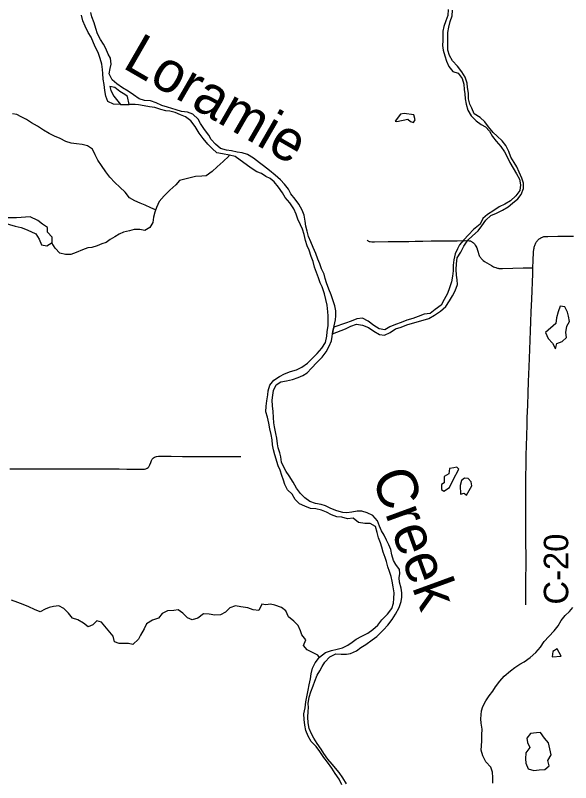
# Model space of a CAD drawing. Extents: x -87 to 2145, y -2128 to 440.
# Drawn here: x 154.2 to 188.26, y -1010.07 to -963.04 of the extents above; entities that cross this region are included whole.
import ezdxf

# ---------------------------------------------------------------- set-up
doc = ezdxf.new("R2010")
doc.units = 0
for name, color, linetype in [('GM_X_County_Road', 7, 'Continuous'), ('GM_X_County_Road_Text', 7, 'Continuous'), ('GM_X_Major_River', 7, 'Continuous'), ('GM_X_Major_River_Text', 7, 'Continuous'), ('GM_X_Minor_Lake', 7, 'Continuous'), ('GM_X_Minor_River', 7, 'Continuous'), ('GM_X_Township_Road', 7, 'Continuous')]:
    doc.layers.add(name, color=color, linetype=linetype)

msp = doc.modelspace()

# ---------------------------------------------------------------- linework, layer by layer
at = {"layer": 'GM_X_County_Road'}
for points in [[(185.948, -978.508), (185.962, -978.073), (185.991, -977.55), (186.009, -977.375), (186.019, -977.311), (186.031, -977.245), (186.046, -977.194), (186.064, -977.138), (186.083, -977.085), (186.105, -977.036), (186.128, -976.989), (186.151, -976.95), (186.171, -976.919), (186.203, -976.876), (186.236, -976.835), (186.267, -976.8), (186.298, -976.77), (186.339, -976.735), (186.38, -976.706), (186.428, -976.677), (186.479, -976.649), (186.536, -976.626), (186.581, -976.61), (186.623, -976.6), (186.679, -976.592), (186.729, -976.589), (186.853, -976.586), (187.475, -976.572), (188.147, -976.569), (188.443, -976.566)], [(185.534, -990.215), (185.537, -989.924), (185.548, -989.514), (185.573, -988.727), (185.588, -988.203), (185.604, -987.711), (185.634, -986.924), (185.658, -986.187), (185.685, -985.482), (185.724, -984.581), (185.767, -983.515), (185.806, -982.368), (185.827, -981.827), (185.85, -981.221), (185.881, -980.434), (185.936, -978.877), (185.948, -978.508)], [(185.517, -999.171), (185.52, -997.581), (185.525, -996.728), (185.525, -996.154), (185.518, -995.4), (185.518, -994.596), (185.516, -993.941), (185.521, -992.99), (185.518, -992.318), (185.517, -991.99), (185.523, -991.301), (185.53, -990.613), (185.534, -990.215)]]:
    msp.add_lwpolyline(points, dxfattribs=at)
at = {"layer": 'GM_X_Major_River'}
for p, q in [((161.172, -968.496), (161.07, -968.011)), ((160.646, -968.494), (161.172, -968.496)), ((161.551, -968.503), (161.172, -968.496))]:
    msp.add_line(p, q, dxfattribs=at)
for points in [[(158.338, -963.372), (158.265, -963.018)], [(170.175, -988.673), (170.092, -988.268), (170.057, -988.016), (170.033, -987.683), (170.009, -987.33), (169.975, -986.976), (169.962, -986.634), (169.988, -986.312), (170.043, -986.041), (170.201, -985.681), (170.475, -985.495), (170.828, -985.431), (171.191, -985.367), (171.555, -985.243), (171.839, -985.107), (172.093, -984.941), (172.359, -984.663), (172.687, -984.317), (173.015, -983.981), (173.272, -983.663), (173.459, -983.314), (173.586, -982.994), (173.641, -982.723), (173.677, -982.401), (173.754, -982.07), (173.841, -981.709), (173.856, -981.447), (173.851, -981.145), (173.797, -980.852), (173.702, -980.527), (173.578, -980.172), (173.434, -979.817), (173.28, -979.441), (173.205, -979.158), (173.14, -978.905), (172.975, -978.569), (172.87, -978.275), (172.755, -977.991), (172.631, -977.636), (172.467, -977.27), (172.322, -976.925), (172.188, -976.59), (172.104, -976.266), (172.019, -975.952), (171.984, -975.649), (171.921, -975.295), (171.796, -974.97), (171.592, -974.614), (171.367, -974.297), (171.101, -973.97), (170.946, -973.695), (170.7, -973.388), (170.474, -973.122), (170.138, -972.833), (169.782, -972.545), (169.425, -972.266), (169.168, -972.069), (168.801, -971.801), (168.434, -971.562), (168.114, -971.465), (167.813, -971.429), (167.463, -971.352), (167.143, -971.296), (166.783, -971.199), (166.486, -970.931), (166.21, -970.654), (166.064, -970.389), (165.81, -970.032), (165.565, -969.674), (165.42, -969.41), (165.094, -969.091), (164.755, -968.964), (164.394, -968.927), (164.064, -968.83), (163.804, -968.755), (163.525, -968.659), (163.175, -968.561), (162.836, -968.394), (162.487, -968.287), (162.126, -968.26), (161.786, -968.152), (161.449, -967.914), (161.122, -967.687), (160.774, -967.479), (160.427, -967.23), (160.13, -966.993), (159.956, -966.627), (160.012, -966.285), (160.067, -966.024), (160.034, -965.671), (159.898, -965.417), (159.754, -965.071), (159.608, -964.807), (159.432, -964.511), (159.248, -964.165), (159.133, -963.851), (159.029, -963.496), (158.895, -963.131), (158.82, -962.857)], [(160.646, -968.494), (160.223, -968.476), (159.864, -968.318), (159.75, -967.983), (159.686, -967.639), (159.652, -967.276), (159.588, -966.952), (159.564, -966.599), (159.539, -966.347), (159.495, -966.034), (159.4, -965.689), (159.277, -965.324), (159.112, -964.999), (158.997, -964.715), (158.852, -964.369), (158.667, -964.084), (158.473, -963.697), (158.338, -963.372)], [(161.07, -968.011), (160.907, -967.894), (160.609, -967.697), (160.292, -967.459), (159.992, -967.393), (160.057, -967.646), (160.242, -967.992), (160.646, -968.494)], [(169.661, -987.676), (169.567, -987.341), (169.583, -986.989), (169.63, -986.658), (169.677, -986.296), (169.701, -986.044), (169.818, -985.714), (170.055, -985.396), (170.401, -985.181), (170.715, -985.015), (171.08, -984.861), (171.443, -984.757), (171.768, -984.612), (172.114, -984.357), (172.717, -983.773), (173.005, -983.436), (173.232, -983.098), (173.3, -982.696), (173.325, -982.435), (173.383, -982.043), (173.398, -981.761), (173.383, -981.458), (173.358, -981.206), (173.335, -980.793), (173.241, -980.458), (173.167, -980.104), (173.014, -979.688), (172.899, -979.434), (172.804, -979.13), (172.669, -978.795), (172.545, -978.47), (172.471, -978.126), (172.346, -977.812), (172.232, -977.437), (172.107, -977.163), (172.002, -976.838), (171.919, -976.464), (171.804, -976.149), (171.689, -975.875), (171.535, -975.53), (171.43, -975.215), (171.275, -974.89), (171.031, -974.523), (170.745, -974.205), (170.58, -973.91), (170.345, -973.573), (170.08, -973.235), (169.823, -973.029), (169.564, -972.913), (169.296, -972.737), (169.017, -972.621), (168.659, -972.413), (168.352, -972.175), (167.995, -971.916), (167.688, -971.699), (167.328, -971.612), (166.907, -971.533), (166.567, -971.456), (166.27, -971.209), (166.014, -970.942), (165.719, -970.584), (165.474, -970.267), (165.23, -969.849), (164.955, -969.512), (164.629, -969.264), (164.32, -969.127), (164.001, -969), (163.671, -968.913), (163.42, -968.899), (163.12, -968.812), (162.761, -968.685), (162.43, -968.638), (162.109, -968.592), (161.759, -968.525), (161.551, -968.503)], [(174.235, -1010.198), (174.071, -1009.853), (173.826, -1009.506), (173.611, -1009.179), (173.356, -1008.822), (173.121, -1008.525), (172.886, -1008.168), (172.661, -1007.862), (172.355, -1007.554), (172.151, -1007.218), (172.016, -1006.873), (171.962, -1006.549), (171.918, -1006.206), (171.905, -1005.853), (171.972, -1005.492), (172.019, -1005.12), (172.153, -1004.397), (172.219, -1004.066), (172.306, -1003.715), (172.352, -1003.393), (172.419, -1003.052), (172.596, -1002.723), (172.863, -1002.385), (173.22, -1002.1), (173.584, -1001.976), (173.938, -1001.881), (174.271, -1001.807), (174.595, -1001.642), (174.85, -1001.465), (175.105, -1001.269), (175.459, -1001.094), (175.814, -1000.909), (176.12, -1000.683), (176.426, -1000.427), (176.674, -1000.089), (177.022, -999.743), (177.289, -999.405), (177.386, -999.075), (177.411, -998.793), (177.428, -998.441), (177.384, -998.067), (177.321, -997.713), (177.245, -997.44), (177.14, -997.136), (177.056, -996.842), (176.961, -996.518), (176.875, -996.264), (176.771, -995.94), (176.676, -995.646), (176.591, -995.372), (176.466, -995.058), (176.391, -994.734), (176.288, -994.379), (175.97, -994.192), (175.628, -994.186), (175.247, -994.128), (174.931, -993.86), (174.568, -993.904), (174.229, -993.807), (173.918, -993.771), (173.599, -993.654), (173.28, -993.497), (172.971, -993.37), (172.641, -993.293), (172.3, -993.257), (171.961, -993.119), (171.632, -992.982), (171.356, -992.705), (171.171, -992.389), (170.894, -992.122), (170.72, -991.796), (170.654, -991.533), (170.549, -991.249), (170.445, -990.915), (170.329, -990.65), (170.121, -989.982), (170.036, -989.678), (169.981, -989.364), (169.947, -989.051), (169.883, -988.728), (169.809, -988.374), (169.755, -988.03), (169.661, -987.676)], [(174.507, -1010.143), (174.293, -1009.776), (174.068, -1009.45), (173.636, -1008.938), (173.36, -1008.631), (173.125, -1008.294), (172.959, -1008.029), (172.705, -1007.681), (172.51, -1007.335), (172.364, -1007.081), (172.23, -1006.746), (172.166, -1006.412), (172.132, -1006.049), (172.158, -1005.717), (172.173, -1005.465), (172.168, -1005.213), (172.225, -1004.841), (172.322, -1004.501), (172.469, -1004.131), (172.565, -1003.86), (172.712, -1003.49), (172.868, -1003.211), (173.014, -1002.952), (173.179, -1002.693), (173.497, -1002.367), (173.852, -1002.182), (174.193, -1002.199), (174.514, -1002.205), (174.767, -1002.149), (175.131, -1001.984), (175.396, -1001.788), (175.691, -1001.602), (176.078, -1001.327), (176.373, -1001.111), (176.783, -1000.696), (177.039, -1000.408), (177.307, -1000.061), (177.524, -999.742), (177.742, -999.343), (177.87, -998.973), (177.905, -998.702), (177.9, -998.43), (177.865, -998.157), (177.771, -997.782), (177.746, -997.51), (177.781, -997.259), (177.756, -997.006), (177.53, -996.7), (177.404, -996.446), (177.3, -996.111), (177.236, -995.777), (177.111, -995.493), (176.975, -995.208), (176.831, -994.893), (176.655, -994.628), (176.529, -994.344), (176.415, -994.019), (176.13, -993.691), (175.781, -993.523), (175.461, -993.427), (175.16, -993.421), (174.847, -993.486), (174.535, -993.54), (174.284, -993.516), (173.924, -993.418), (173.556, -993.27), (173.217, -993.103), (172.957, -993.027), (172.607, -992.95), (172.258, -992.833), (171.95, -992.615), (171.684, -992.338), (171.439, -992.011), (171.245, -991.645), (171.001, -991.257), (170.805, -991.002), (170.65, -990.687), (170.524, -990.432), (170.48, -990.109), (170.414, -989.856), (170.329, -989.552), (170.284, -989.299), (170.23, -988.946), (170.175, -988.673)]]:
    msp.add_lwpolyline(points, dxfattribs=at)
at = {"layer": 'GM_X_Minor_Lake'}
for points in [[(178.043, -969.045), (177.831, -969.101), (177.501, -969.528), (177.601, -969.55), (178.267, -969.403)], [(178.267, -969.403), (178.434, -969.547), (178.624, -969.602), (178.718, -969.442), (178.634, -969.128), (178.043, -969.045)], [(155.114, -975.379), (154.278, -975.448), (153.967, -975.441), (153.645, -975.455), (153.394, -975.48), (153.499, -975.754), (153.848, -975.862), (154.198, -975.95), (154.557, -976.048), (154.816, -976.144), (155.155, -976.282), (155.463, -976.43)], [(155.463, -976.43), (155.657, -976.766), (155.8, -977.112), (156.121, -977.159), (156.466, -976.965), (156.453, -976.642), (156.178, -976.334), (156.174, -976.032), (155.867, -975.844), (155.571, -975.606), (155.114, -975.379)], [(188.031, -982.099), (188.182, -981.802), (188.133, -981.479), (188.072, -981.225), (187.912, -980.897), (187.623, -980.856), (187.49, -981.204), (187.387, -981.582), (187.345, -981.923)], [(187.345, -981.923), (186.713, -982.484), (186.88, -982.853), (187.141, -983.134), (187.33, -983.483), (187.422, -983.144), (187.747, -983.035), (188.016, -982.793), (187.968, -982.469), (188.031, -982.099)], [(181.057, -991.502), (181.4, -990.86), (181.275, -990.724), (181.092, -990.778), (180.83, -990.809), (180.799, -991.14), (180.512, -991.311)], [(180.512, -991.311), (180.498, -991.683), (180.344, -991.798), (180.343, -992.1), (180.49, -992.196), (180.829, -991.987), (181.057, -991.502)], [(182.198, -991.875), (182.166, -991.642), (181.982, -991.434), (181.742, -991.416), (181.567, -991.55), (181.486, -991.86)], [(181.486, -991.86), (181.497, -992.393), (181.72, -992.331), (181.876, -992.457), (182.198, -991.875)], [(187.168, -1002.03), (187.127, -1002.361), (187.674, -1002.318)], [(187.674, -1002.318), (187.445, -1001.859), (187.168, -1002.03)], [(186.333, -1009.279), (186.673, -1009.259), (186.952, -1009.038), (186.853, -1008.712), (187.066, -1008.358), (186.978, -1007.992), (186.911, -1007.637), (186.65, -1007.346), (186.421, -1007.006), (186.17, -1007.017), (185.807, -1007.064)], [(185.807, -1007.064), (185.566, -1007.347), (185.617, -1007.601), (185.757, -1007.918), (185.514, -1008.251), (185.502, -1008.603), (185.522, -1008.876), (185.661, -1009.223), (186.008, -1009.336), (186.333, -1009.279)]]:
    msp.add_lwpolyline(points, dxfattribs=at)
at = {"layer": 'GM_X_Minor_River'}
msp.add_line((178.205, -982.012), (179.569, -981.613), dxfattribs=at)
for points in [[(180.757, -962.68), (180.724, -963.041), (180.602, -963.379), (180.489, -963.727), (180.429, -963.997), (180.428, -964.319), (180.419, -964.57), (180.408, -964.892), (180.438, -965.165), (180.546, -965.521), (180.646, -965.837), (180.784, -966.174), (181.044, -966.485), (181.372, -966.588), (181.612, -966.898), (181.7, -967.254), (181.738, -967.587), (181.779, -967.84), (181.798, -968.153), (181.847, -968.487), (181.955, -968.843), (182.153, -969.203), (182.464, -969.496), (182.767, -969.718), (183.032, -969.879), (183.284, -970.14), (183.473, -970.469), (183.694, -970.758), (183.974, -971.07), (184.213, -971.401), (184.391, -971.75), (184.541, -972.067), (184.73, -972.396), (184.948, -972.746), (185.127, -973.085), (185.185, -973.419), (185.153, -973.771), (184.9, -974.104), (184.579, -974.404), (184.23, -974.613), (183.883, -974.782), (183.544, -975.001), (183.165, -975.239), (182.885, -975.481), (182.702, -975.827), (182.309, -976.155), (181.996, -976.496), (181.715, -976.798), (181.443, -977.1), (181.314, -977.357), (181.173, -977.664), (181.09, -978.024), (181.058, -978.355), (181.046, -978.706), (181.024, -979.028), (180.952, -979.368), (180.838, -979.746), (180.716, -980.094), (180.513, -980.449), (180.31, -980.794), (179.959, -981.063), (179.639, -981.313)], [(180.277, -981.165), (180.598, -980.885), (180.831, -980.531), (181.012, -980.225), (181.173, -979.929), (181.327, -979.542), (181.297, -979.259), (181.268, -978.956), (181.24, -978.613), (181.252, -978.261), (181.305, -977.9), (181.518, -977.556), (181.711, -977.19), (181.945, -976.826), (182.245, -976.555), (182.587, -976.255), (182.819, -975.931), (183.062, -975.598), (183.373, -975.307), (183.719, -975.159), (184.077, -974.98), (184.425, -974.781), (184.704, -974.55), (185.015, -974.279), (185.224, -974.025), (185.378, -973.658), (185.37, -973.315), (185.26, -973.009), (185.112, -972.642), (184.953, -972.324), (184.792, -972.056), (184.593, -971.727), (184.464, -971.38), (184.296, -971.022), (184.056, -970.731), (183.755, -970.438), (183.502, -970.208), (183.213, -969.875), (182.993, -969.555), (182.712, -969.293), (182.348, -969.069), (182.199, -968.731), (182.078, -968.475), (181.999, -968.15), (181.991, -967.808), (181.943, -967.454), (181.912, -967.201), (181.795, -966.824), (181.596, -966.495), (181.317, -966.153), (181.007, -965.819), (180.828, -965.501), (180.729, -965.165), (180.721, -964.823), (180.734, -964.461), (180.737, -964.088), (180.789, -963.758), (180.871, -963.419), (180.984, -963.06), (181.016, -962.729)], [(162.801, -974.967), (162.516, -974.835), (162.168, -974.677), (161.859, -974.549), (161.531, -974.411), (161.203, -974.233), (160.939, -973.885), (160.615, -973.566), (160.299, -973.277), (159.985, -972.948), (159.741, -972.621), (159.487, -972.243), (159.253, -971.916), (159.089, -971.59), (158.926, -971.244), (158.629, -971.026), (158.299, -970.959), (157.959, -970.911), (157.618, -970.874), (157.288, -970.776), (156.951, -970.588), (156.593, -970.439), (156.265, -970.271), (155.917, -970.072), (155.551, -969.833), (155.183, -969.624), (154.876, -969.426), (154.559, -969.248), (154.29, -969.122), (154.03, -969.066)], [(167.313, -971.609), (167.303, -971.661), (166.944, -972.006), (166.586, -972.331), (166.268, -972.617), (165.901, -972.881), (165.63, -972.885), (165.258, -972.908), (164.915, -972.991), (164.602, -973.086), (164.278, -973.169), (164.042, -973.426), (163.684, -973.751), (163.325, -974.106), (163.026, -974.453), (162.858, -974.822), (162.752, -975.092), (162.675, -975.413), (162.628, -975.734), (162.451, -976.032), (162.146, -976.228), (161.826, -976.16), (161.494, -976.174), (161.211, -976.248), (160.838, -976.331), (160.564, -976.456), (160.31, -976.612), (160.015, -976.787), (159.76, -976.953), (159.508, -977.039), (159.214, -977.163), (158.9, -977.258), (158.649, -977.293), (158.315, -977.406), (157.93, -977.57), (157.606, -977.704), (157.285, -977.687), (156.924, -977.619), (156.65, -977.311), (156.427, -976.987)], [(179.639, -981.313), (179.273, -981.347), (178.918, -981.502), (178.584, -981.627), (178.221, -981.731), (177.857, -981.855), (177.513, -981.989), (177.178, -982.134), (176.854, -982.31), (176.523, -982.243), (176.185, -982.045), (175.849, -981.777), (175.5, -981.609), (175.138, -981.643), (174.794, -981.787), (174.46, -981.902), (173.737, -982.143)], [(179.569, -981.613), (179.907, -981.414), (180.277, -981.165)], [(173.658, -982.569), (174.454, -982.244), (174.788, -982.089), (175.132, -981.965), (175.492, -982.032), (175.852, -982.17), (176.189, -982.388), (176.537, -982.606), (176.837, -982.642), (177.192, -982.487), (177.518, -982.251), (177.861, -982.147), (178.205, -982.012)], [(173.737, -982.143), (173.677, -982.401), (173.658, -982.569)], [(160.199, -1001.09), (159.474, -1000.238), (159.205, -1000.152), (158.949, -1000.388), (158.664, -1000.523), (158.388, -1000.286), (158.031, -1000.087), (157.702, -999.979), (157.467, -999.692), (157.181, -999.404), (156.874, -999.237), (156.541, -999.28), (156.279, -999.345), (156.026, -999.43), (155.731, -999.606), (155.382, -999.467), (155.025, -999.299), (154.686, -999.16), (154.347, -999.033), (153.969, -998.884)], [(172.851, -1002.401), (172.758, -1002.26), (172.391, -1002.071), (172.102, -1001.934), (171.877, -1001.657), (172.015, -1001.307), (171.78, -1001.01), (171.695, -1000.757), (171.541, -1000.431), (171.276, -1000.174), (170.96, -999.905), (170.797, -999.549), (170.53, -999.342), (170.111, -999.202), (169.841, -999.136), (169.569, -999.171), (169.309, -999.125), (169.14, -999.514), (168.779, -999.487), (168.451, -999.359), (168.03, -999.3), (167.71, -999.243), (167.366, -999.356), (167.099, -999.623), (166.775, -999.777), (166.443, -999.8), (166.092, -999.753), (165.732, -999.715), (165.394, -999.99), (165.051, -1000.083), (164.752, -999.966), (164.467, -999.678), (164.18, -999.481), (163.928, -999.516), (163.526, -999.538), (163.201, -999.712), (162.974, -999.999), (162.62, -1000.113), (162.254, -1000.337), (162.097, -1000.646), (161.878, -1001.024), (161.762, -1001.284), (161.404, -1001.598), (161.134, -1001.542), (160.813, -1001.536), (160.561, -1001.54), (160.282, -1001.444), (160.199, -1001.09)], [(183.482, -1010.101), (183.494, -1009.759), (183.476, -1009.426), (183.366, -1009.12), (183.067, -1008.787), (182.869, -1008.418), (182.781, -1008.073), (182.79, -1007.821), (182.821, -1007.5), (182.824, -1007.138), (182.826, -1006.786), (182.769, -1006.421), (182.758, -1006.169), (182.767, -1005.918), (182.796, -1005.667), (182.885, -1005.409), (183.058, -1005.063), (183.269, -1004.748), (183.48, -1004.464), (183.66, -1004.199), (183.913, -1003.855), (184.185, -1003.553), (184.578, -1003.215), (184.835, -1003.023), (185.154, -1002.813), (185.42, -1002.662), (185.781, -1002.393), (186.122, -1002.103), (186.405, -1001.761), (186.628, -1001.417), (186.92, -1001.105), (187.243, -1000.774), (187.505, -1000.462), (187.677, -1000.136), (187.928, -999.833), (188.188, -999.58), (188.388, -999.326)]]:
    msp.add_lwpolyline(points, dxfattribs=at)
at = {"layer": 'GM_X_Township_Road'}
for points in [[(175.78, -976.827), (175.806, -976.847), (175.833, -976.864), (175.863, -976.879), (175.9, -976.892), (175.934, -976.902), (175.974, -976.907), (176.072, -976.915), (176.236, -976.919), (177.072, -976.906), (177.614, -976.903), (178.335, -976.894), (178.729, -976.883), (179.19, -976.877), (179.696, -976.869), (180.432, -976.857), (180.776, -976.856), (181.3, -976.858), (181.841, -976.848), (182.043, -976.852), (182.088, -976.858), (182.121, -976.866), (182.146, -976.876), (182.171, -976.89), (182.209, -976.913), (182.246, -976.937), (182.298, -976.978), (182.327, -977.004), (182.354, -977.036), (182.412, -977.116), (182.452, -977.187), (182.499, -977.294), (182.547, -977.43), (182.581, -977.544), (182.611, -977.653), (182.627, -977.704), (182.645, -977.75), (182.66, -977.782), (182.688, -977.826), (182.712, -977.865), (182.743, -977.903), (182.774, -977.941), (182.855, -978.022), (182.905, -978.064), (182.985, -978.122), (183.122, -978.211), (183.403, -978.377), (183.532, -978.445), (183.601, -978.479), (183.664, -978.503), (183.716, -978.52), (183.766, -978.534), (183.816, -978.544), (183.866, -978.551), (183.917, -978.556), (183.972, -978.559), (184.087, -978.561), (185.349, -978.521), (185.775, -978.512), (185.948, -978.508)], [(153.867, -990.837), (154.293, -990.837), (154.933, -990.832), (155.392, -990.834), (155.917, -990.832), (156.163, -990.833), (156.639, -990.837), (157.098, -990.835), (157.524, -990.832), (158.574, -990.839), (159.755, -990.842), (160.197, -990.845), (160.574, -990.844), (161.034, -990.85), (161.624, -990.861), (162.033, -990.858), (162.128, -990.849), (162.205, -990.832), (162.277, -990.803), (162.341, -990.76), (162.383, -990.717), (162.41, -990.681), (162.452, -990.597), (162.504, -990.443), (162.543, -990.332), (162.592, -990.242), (162.649, -990.176), (162.676, -990.154), (162.734, -990.117), (162.798, -990.091), (162.864, -990.073), (162.982, -990.058), (163.148, -990.052), (163.345, -990.053), (163.755, -990.067), (164.443, -990.077), (165.148, -990.077), (165.903, -990.077), (166.723, -990.075), (167.215, -990.075), (167.526, -990.073), (167.837, -990.072), (168.033, -990.074)]]:
    msp.add_lwpolyline(points, dxfattribs=at)

# ---------------------------------------------------------------- texts
at = {"layer": 'GM_X_County_Road_Text'}
msp.add_text('C-20', height=1.5, rotation=90, dxfattribs=at).set_placement((188.114, -999.155))
at = {"layer": 'GM_X_Major_River_Text'}
for s, height, rotation, p in [('Loramie', 2.4998, 330.0316, (160.706, -966.213)), ('Creek', 2.4989, 290.0285, (176.037, -991.285))]:
    msp.add_text(s, height=height, rotation=rotation, dxfattribs=at).set_placement(p)

doc.saveas('drawing.dxf')
